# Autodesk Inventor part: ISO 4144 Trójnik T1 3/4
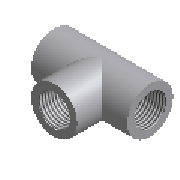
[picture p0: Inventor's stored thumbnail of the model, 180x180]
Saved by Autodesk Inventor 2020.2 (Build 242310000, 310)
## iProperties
Manager: www.cadconsulting.pl
Company: Fabian Stasiak CAD Consulting
NAME: PIPING: ISO 4144 Tee B1
DATA: <meta><inlinegroups number="1" deflen="5.6"></inlinegroups><connections number="3"></connections><angles><a>3.14159265358979</a><a>1.5707963267949</a></angles><
IsCustomPart: 0
Created: 2014-02
Part Number: ISO 4144 Trójnik T1 3/4
Material: Stal nierdzewna
Description: Rurociągi - Elementy ze stali nierdzewnej gwintowane zgodnie z ISO 7-1
Document SubType Name: Modeling
Standard: ISO 4144
Designer: F.Stasiak
Standard Revision: Second edition 2003-03-15
Standards Organization: ISO
Language: pl-PL
Size Designation: 3/4
Categories: <MemberInstance><Categories><Category DisplayName="Rury cienko- i grubościenne" InternalName="4347fa0f-2144-441d-94cd-e3e15c92b736" Mnemonic="TUBEANDPIPE"><Cate
Density: 1 g/cm^3
Appearance: Częściowo polerowana
Catalog Web Link: www.expertbooks.pl
Author: F.Stasiak
Subject: Zbiór ćwiczeń. Autodesk Inventor 2020. Kurs Professional
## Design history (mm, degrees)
sketch "Sketch1"
  geometry: L1 (0, 0)-(66, 0); L2 (66, 0)-(66, 12.059); L3 (33, 0)-(33, 16.25); L4 (0, 0)-(0, 12.059); L5 (0, 12.059)-(14.1, 11.618); L6 (66, 12.059)-(51.9, 11.618); L7 (0, 12.059)-(0, 16.25); L8 (66, 12.059)-(66, 16.25); L9 (14.1, 11.618)-(51.9, 11.618); L10 (0, 16.25)-(66, 16.25); L11 (14.1, 11.618)-(14.1, 0); L12 (51.9, 11.618)-(51.9, 0)
  constraints: 24 end point, 4 perpendicular, 2 midpoint, 2 parallel, 2 point on line, 2 symmetric about line, 1 horizontal, 3 other
  dimensions: "d0" = 24.117 diameter of L4.end L1 (= MD); "d1" = 14.1 horizontal distance of L4.end L5.end (= L); "d2" = 33 distance between parallel lines of L3 L4 (= a); "d3" = 1.78991 deg angle of L1 L5; "d10" = 32.5 diameter of L10 L1 (= d)
revolve "Revolution1" sketch "Sketch1" stored, may be unused: angle "d8" = 90 deg
workplane "Work Plane1"
sketch "Sketch2"
  geometry: L1 (0, 0)-(66, 0) reference; L2 (33, 0)-(33, 16.25) reference; C1 r 16.25 at (33, 0); C2 r 12.059 at (33, 0)
  constraints: 2 centre point, 1 coincident, 1 concentric, 1 point on line
  dimensions: "d5" = 32.5 diameter of C1 (= d); "d7" = 24.117 diameter of C2 (= MD)
extrude "Extrusion1" join sketch "Sketch2" taper "d6" = 0 deg; stored distance "d11" = 10
extrude "Extrusion2" cut sketch "Sketch2" taper "d9" = -1.78991 deg; stored distance "d17" = 7.05 (= 0.5 x L)
workplane "Work Plane2"
sketch "Sketch3"
  geometry: L1 (66, 0)-(0, 0) reference; L2 (33, 0)-(33, 33); L3 (33, 33)-(18.9, 33); L4 (18.9, 33)-(18.9, 18.9); L5 (18.9, 18.9)-(33, 18.9)
  constraints: 8 end point, 4 perpendicular, 1 midpoint, 1 point on line
  dimensions: "d42" = 33 distance of L2.start L2.end (= a); "d43" = 14.1 distance of L2.end L3.end (= L); "d44" = 14.1 distance of L3.end L4.end (= L)
workpoint "Work Point2"
workpoint "Work Point3"
workpoint "Work Point4"
workaxis "Work Axis2"
workpoint "Work Point5"
workaxis "Work Axis3"
workaxis "Work Axis4"
workpoint "Work Point6"
workaxis "Work Axis5"
workpoint "Work Point7"
body "Solid1"
feature "Gwint1" dims "d23" = 10, "d24" = 0
feature "Gwint2" dims "d25" = 10, "d26" = 0
feature "Gwint3" dims "d12" = 14.1 (= L), "d13" = 0
other parameters: "a" = 33 [user parameter; used in 3 equation terms], "d" = 32.5 [user parameter; used in 2 equation terms], "MD" = 24.117 [user parameter; used in 2 equation terms], "L" = 14.1 [user parameter; used in 5 equation terms], "d4" = 33 (= a), "Size_Designation" = 7.5 [user parameter]
